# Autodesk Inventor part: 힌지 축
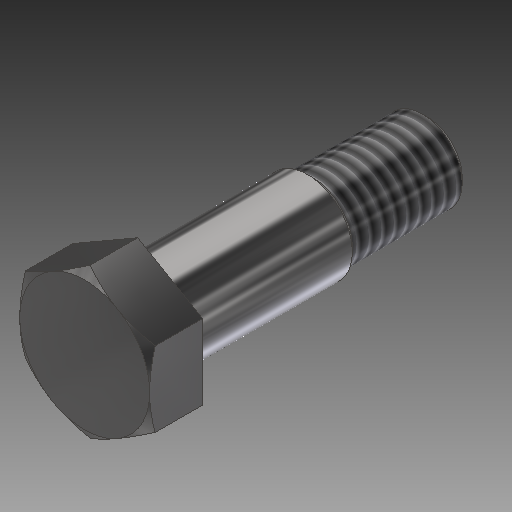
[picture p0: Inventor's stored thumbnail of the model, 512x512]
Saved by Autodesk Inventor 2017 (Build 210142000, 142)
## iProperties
Created: 2019-09
Part Number: 힌지 축
Material: 스테인리스강
Document SubType Name: Modeling
Designer: mduedu
Density: 8.08 g/cm^3
Appearance: 반광택
Mass: 19.8099 g
Surface Area: 13.175 cm^2
Volume: 2.45172 cm^3
Author: mduedu
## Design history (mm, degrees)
sketch "스케치1"
  geometry: C1 r 4 at (0, 0); 1 further point
  constraints: 1 centre point, 1 coincident
  dimensions: "d0" = 8 diameter of C1
extrude "돌출1" new body sketch "스케치1" distance "d1" = 29; taper "d2" = 0 deg
sketch "스케치2"
  geometry: C1 r 4.5 at (0, 0); 1 further point
  constraints: 1 centre point, 1 coincident
  dimensions: "d3" = 9 diameter of C1
extrude "돌출2" join sketch "스케치2" distance "d4" = 17.5; taper "d5" = 0 deg
sketch "스케치3"
  geometry: L1 (0, 7.506)-(6.5, 3.753); L2 (6.5, 3.753)-(6.5, -3.753); L3 (6.5, -3.753)-(0, -7.506); L4 (0, -7.506)-(-6.5, -3.753); L5 (-6.5, -3.753)-(-6.5, 3.753); L6 (-6.5, 3.753)-(0, 7.506); C1 r 6.5 at (0, 0); 2 further points
  constraints: 12 end point, 2 coincident, 1 centre point, 1 tangent, 1 vertical alignment, 13 other
  dimensions: "d6" = 6.5 radius of C1
extrude "돌출3" join sketch "스케치3" distance "d8" = 5.3; taper "d9" = 0 deg
sketch "스케치4"
  geometry: L1 (-4, 11.5)-(-4.5, 11.5) reference; L2 (-4.5, 11.5)-(-4.5, 29) reference; L3 (-4.5, 29)-(-7.506, 29) reference; L4 (-7.506, 29)-(-7.506, 34.3) reference; L5 (-7.506, 34.3)-(7.506, 34.3) reference; L6 (7.506, 34.3)-(7.506, 29) reference; L7 (7.506, 29)-(4.5, 29) reference; L8 (4.5, 29)-(4.5, 11.5) reference; L9 (4.5, 11.5)-(4, 11.5) reference; L10 (4, 11.5)-(4, 0) reference; L11 (4, 0)-(-4, 0) reference; L12 (-4, 0)-(-4, 11.5) reference; L13 (0, 0)-(0, 34.3); L14 (7.506, 34.3)-(7.506, 33.746); L15 (6.506, 34.3)-(7.506, 33.746); L16 (7.506, 34.3)-(6.506, 34.3); L17 (4.5, 29)-(4, 29); L18 (4, 29)-(4, 28.5); L19 (4, 28.5)-(4.5, 28.5); L20 (4.5, 28.5)-(4.5, 29)
  constraints: 16 end point, 2 parallel, 2 perpendicular, 2 point on line, 1 horizontal, 1 midpoint
  dimensions: "d10" = 1 distance of L5.end L15.start; "d11" = 29 deg angle of L15 L5; "d12" = 0.5 distance of L19.end L7.end; "d13" = 0.5 distance of L18.end L19.end
revolve "회전1" sketch "스케치4" stored, may be unused: angle "d14" = 90 deg
feature "스레드1" dims "d15" = 10, "d16" = 0
chamfer "모따기1" distance "d17" = 0.5; stored, may be unused: second distance "d18" = 2, angle "d19" = 45 deg
chamfer "모따기2" distance "d20" = 0.5; stored, may be unused: second distance "d21" = 2, angle "d22" = 45 deg
node "솔리드1"
node "절단 모서리 투영1"
